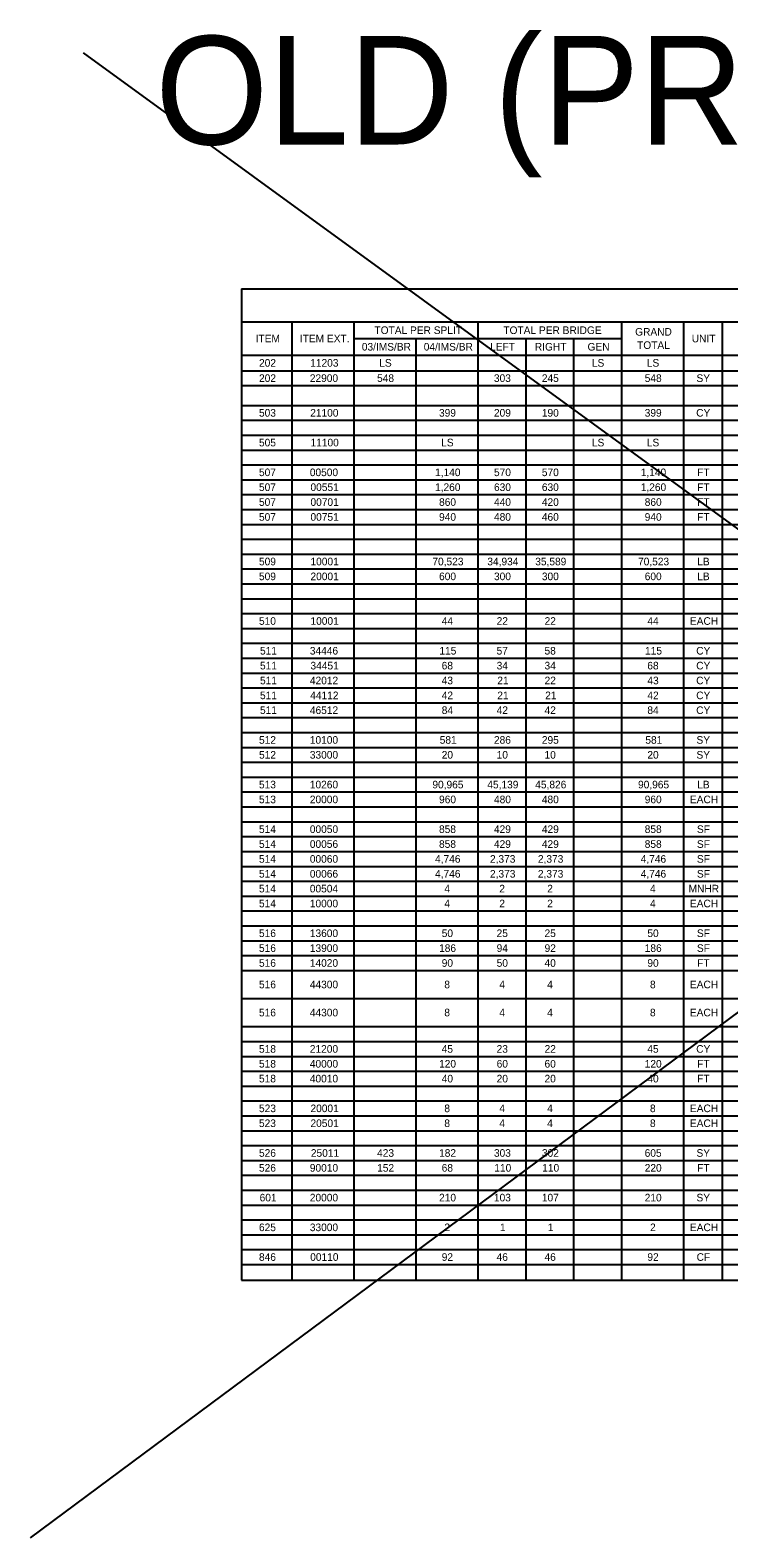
# Model space of a CAD drawing. Extents: x -62.6 to 33.3, y -2.9 to 24.9.
# Drawn here: x -62.61 to -49.74, y -2.88 to 24.89 of the extents above; entities that cross this region are included whole.
import ezdxf

# ---------------------------------------------------------------- set-up
doc = ezdxf.new("R2010")
doc.units = 0
doc.layers.add('Default', color=7, linetype='Continuous')
doc.layers.add('SH_Major_Grid_Line', color=7, linetype='Continuous')

msp = doc.modelspace()

# ---------------------------------------------------------------- linework, layer by layer
at = {"layer": 'Default'}
for p, q in [((-58.718, 20.126), (-29.957, 20.126)), ((-58.718, 20.126), (-58.718, 1.866)), ((-58.718, 19.518), (-29.957, 19.518)), ((-57.79, 19.518), (-57.79, 1.866)), ((-56.649, 19.518), (-56.649, 1.866)), ((-54.366, 19.518), (-54.366, 1.866)), ((-51.718, 19.518), (-51.718, 1.866)), ((-50.577, 19.518), (-50.577, 1.866)), ((-49.862, 19.518), (-49.862, 1.866)), ((-56.649, 19.213), (-51.718, 19.213)), ((-55.507, 19.213), (-55.507, 1.866)), ((-53.483, 19.213), (-53.483, 1.866)), ((-52.601, 19.213), (-52.601, 1.866)), ((-58.718, 18.909), (-29.957, 18.909)), ((-58.718, 18.62), (-29.957, 18.62)), ((-58.718, 18.346), (-29.957, 18.346)), ((-58.718, 17.981), (-29.957, 17.981)), ((-58.718, 17.707), (-29.957, 17.707)), ((-58.718, 17.433), (-29.957, 17.433)), ((-58.718, 17.159), (-29.957, 17.159)), ((-58.718, 16.885), (-29.957, 16.885)), ((-58.718, 16.611), (-29.957, 16.611)), ((-58.718, 16.337), (-29.957, 16.337)), ((-58.718, 16.063), (-29.957, 16.063)), ((-58.718, 15.789), (-29.957, 15.789)), ((-58.718, 15.516), (-29.957, 15.516)), ((-58.718, 15.242), (-29.957, 15.242)), ((-58.718, 14.968), (-29.957, 14.968)), ((-58.718, 14.694), (-29.957, 14.694)), ((-58.718, 14.42), (-29.957, 14.42)), ((-58.718, 14.146), (-29.957, 14.146)), ((-58.718, 13.872), (-29.957, 13.872)), ((-58.718, 13.598), (-29.957, 13.598)), ((-58.718, 13.324), (-29.957, 13.324)), ((-58.718, 13.05), (-29.957, 13.05)), ((-58.718, 12.776), (-29.957, 12.776)), ((-58.718, 12.502), (-29.957, 12.502)), ((-58.718, 12.229), (-29.957, 12.229)), ((-58.718, 11.955), (-29.957, 11.955)), ((-58.718, 11.681), (-29.957, 11.681)), ((-58.718, 11.407), (-29.957, 11.407)), ((-58.718, 11.133), (-29.957, 11.133)), ((-58.718, 10.859), (-29.957, 10.859)), ((-58.718, 10.585), (-29.957, 10.585)), ((-58.718, 10.311), (-29.957, 10.311)), ((-58.718, 10.037), (-29.957, 10.037)), ((-58.718, 9.763), (-29.957, 9.763)), ((-58.718, 9.489), (-29.957, 9.489)), ((-58.718, 9.216), (-29.957, 9.216)), ((-58.718, 8.942), (-29.957, 8.942)), ((-58.718, 8.668), (-29.957, 8.668)), ((-58.718, 8.394), (-29.957, 8.394)), ((-58.718, 8.12), (-29.957, 8.12)), ((-58.718, 7.846), (-29.957, 7.846)), ((-58.718, 7.572), (-29.957, 7.572)), ((-58.718, 7.055), (-29.957, 7.055)), ((-58.718, 6.537), (-29.957, 6.537)), ((-58.718, 6.263), (-29.957, 6.263)), ((-58.718, 5.989), (-29.957, 5.989)), ((-58.718, 5.716), (-29.957, 5.716)), ((-58.718, 5.442), (-29.957, 5.442)), ((-58.718, 5.168), (-29.957, 5.168)), ((-58.718, 4.894), (-29.957, 4.894)), ((-58.718, 4.62), (-29.957, 4.62)), ((-58.718, 4.346), (-29.957, 4.346)), ((-58.718, 4.072), (-29.957, 4.072)), ((-58.718, 3.798), (-29.957, 3.798)), ((-58.718, 3.524), (-29.957, 3.524)), ((-58.718, 3.25), (-29.957, 3.25)), ((-58.718, 2.976), (-29.957, 2.976)), ((-58.718, 2.702), (-29.957, 2.702)), ((-58.718, 2.429), (-29.957, 2.429)), ((-58.718, 2.155), (-29.957, 2.155)), ((-58.718, 1.866), (-29.957, 1.866))]:
    msp.add_line(p, q, dxfattribs=at)
at = {"layer": 'SH_Major_Grid_Line'}
for p, q in [((-25.522, 24.668), (-62.613, -2.881)), ((-61.637, 24.473), (-25.913, -1.513))]:
    msp.add_line(p, q, dxfattribs=at)

# ---------------------------------------------------------------- texts
for s, height, p in [('OLD (PRIOR TO 9-28-22)', 2, (-60.308, 22.787)), ('ITEM', 0.14, (-58.458, 19.143)), ('ITEM EXT.', 0.14, (-57.644, 19.143)), ('TOTAL PER SPLIT', 0.14, (-56.269, 19.296)), ('TOTAL PER BRIDGE', 0.14, (-53.894, 19.296)), ('GRAND ', 0.14, (-51.466, 19.266)), ('UNIT', 0.14, (-50.423, 19.143)), ('03/IMS/BR', 0.14, (-56.502, 18.991)), ('04/IMS/BR', 0.14, (-55.361, 18.991)), ('LEFT', 0.14, (-54.138, 18.991)), ('RIGHT', 0.14, (-53.314, 18.991)), ('GEN', 0.14, (-52.343, 18.991)), ('TOTAL', 0.14, (-51.43, 19.021)), ('202', 0.14, (-58.396, 18.694)), ('11203', 0.14, (-57.453, 18.694)), ('LS', 0.14, (-56.181, 18.694)), ('LS', 0.14, (-52.263, 18.694)), ('LS', 0.14, (-51.251, 18.694)), ('202', 0.14, (-58.396, 18.413)), ('22900', 0.14, (-57.46, 18.413)), ('548', 0.14, (-56.221, 18.413)), ('303', 0.14, (-54.068, 18.413)), ('245', 0.14, (-53.185, 18.413)), ('548', 0.14, (-51.29, 18.413)), ('SY', 0.14, (-50.336, 18.413)), ('503', 0.14, (-58.397, 17.774)), ('21100', 0.14, (-57.453, 17.774)), ('399', 0.14, (-55.08, 17.774)), ('209', 0.14, (-54.068, 17.774)), ('190', 0.14, (-53.185, 17.774)), ('399', 0.14, (-51.29, 17.774)), ('CY', 0.14, (-50.341, 17.774)), ('505', 0.14, (-58.397, 17.226)), ('11100', 0.14, (-57.447, 17.226)), ('LS', 0.14, (-55.04, 17.226)), ('LS', 0.14, (-52.263, 17.226)), ('LS', 0.14, (-51.251, 17.226)), ('507', 0.14, (-58.397, 16.678)), ('00500', 0.14, (-57.46, 16.678)), ('1,140', 0.14, (-55.153, 16.678)), ('570', 0.14, (-54.067, 16.678)), ('570', 0.14, (-53.185, 16.678)), ('1,140', 0.14, (-51.363, 16.678)), ('FT', 0.14, (-50.325, 16.678)), ('507', 0.14, (-58.397, 16.404)), ('00551', 0.14, (-57.448, 16.404)), ('1,260', 0.14, (-55.153, 16.404)), ('630', 0.14, (-54.067, 16.404)), ('630', 0.14, (-53.185, 16.404)), ('1,260', 0.14, (-51.363, 16.404)), ('FT', 0.14, (-50.325, 16.404)), ('507', 0.14, (-58.397, 16.13)), ('00701', 0.14, (-57.448, 16.13)), ('860', 0.14, (-55.079, 16.13)), ('440', 0.14, (-54.067, 16.13)), ('420', 0.14, (-53.185, 16.13)), ('860', 0.14, (-51.29, 16.13)), ('FT', 0.14, (-50.325, 16.13)), ('507', 0.14, (-58.397, 15.856)), ('00751', 0.14, (-57.448, 15.856)), ('940', 0.14, (-55.079, 15.856)), ('480', 0.14, (-54.067, 15.856)), ('460', 0.14, (-53.185, 15.856)), ('940', 0.14, (-51.29, 15.856)), ('FT', 0.14, (-50.325, 15.856)), ('509', 0.14, (-58.397, 15.035)), ('10001', 0.14, (-57.448, 15.035)), ('70,523', 0.14, (-55.202, 15.035)), ('34,934', 0.14, (-54.19, 15.035)), ('35,589', 0.14, (-53.307, 15.035)), ('70,523', 0.14, (-51.413, 15.035)), ('LB', 0.14, (-50.322, 15.035)), ('509', 0.14, (-58.397, 14.761)), ('20001', 0.14, (-57.448, 14.761)), ('600', 0.14, (-55.079, 14.761)), ('300', 0.14, (-54.067, 14.761)), ('300', 0.14, (-53.185, 14.761)), ('600', 0.14, (-51.29, 14.761)), ('LB', 0.14, (-50.322, 14.761)), ('510', 0.14, (-58.397, 13.939)), ('10001', 0.14, (-57.448, 13.939)), ('44', 0.14, (-55.03, 13.939)), ('22', 0.14, (-54.018, 13.939)), ('22', 0.14, (-53.135, 13.939)), ('44', 0.14, (-51.241, 13.939)), ('EACH', 0.14, (-50.457, 13.939)), ('511', 0.14, (-58.378, 13.391)), ('34446', 0.14, (-57.46, 13.391)), ('115', 0.14, (-55.073, 13.391)), ('57', 0.14, (-54.019, 13.391)), ('58', 0.14, (-53.136, 13.391)), ('115', 0.14, (-51.284, 13.391)), ('CY', 0.14, (-50.341, 13.391)), ('511', 0.14, (-58.378, 13.117)), ('34451', 0.14, (-57.448, 13.117)), ('68', 0.14, (-55.031, 13.117)), ('34', 0.14, (-54.018, 13.117)), ('34', 0.14, (-53.136, 13.117)), ('68', 0.14, (-51.242, 13.117)), ('CY', 0.14, (-50.341, 13.117)), ('511', 0.14, (-58.378, 12.843)), ('42012', 0.14, (-57.459, 12.843)), ('43', 0.14, (-55.031, 12.843)), ('21', 0.14, (-54.006, 12.843)), ('22', 0.14, (-53.135, 12.843)), ('43', 0.14, (-51.241, 12.843)), ('CY', 0.14, (-50.341, 12.843)), ('511', 0.14, (-58.378, 12.569)), ('44112', 0.14, (-57.453, 12.569)), ('42', 0.14, (-55.03, 12.569)), ('21', 0.14, (-54.006, 12.569)), ('21', 0.14, (-53.124, 12.569)), ('42', 0.14, (-51.241, 12.569)), ('CY', 0.14, (-50.341, 12.569)), ('511', 0.14, (-58.378, 12.296)), ('46512', 0.14, (-57.459, 12.296)), ('84', 0.14, (-55.03, 12.296)), ('42', 0.14, (-54.018, 12.296)), ('42', 0.14, (-53.135, 12.296)), ('84', 0.14, (-51.241, 12.296)), ('CY', 0.14, (-50.341, 12.296)), ('512', 0.14, (-58.396, 11.748)), ('10100', 0.14, (-57.46, 11.748)), ('581', 0.14, (-55.067, 11.748)), ('286', 0.14, (-54.068, 11.748)), ('295', 0.14, (-53.185, 11.748)), ('581', 0.14, (-51.278, 11.748)), ('SY', 0.14, (-50.336, 11.748)), ('512', 0.14, (-58.396, 11.474)), ('33000', 0.14, (-57.46, 11.474)), ('20', 0.14, (-55.03, 11.474)), ('10', 0.14, (-54.018, 11.474)), ('10', 0.14, (-53.136, 11.474)), ('20', 0.14, (-51.241, 11.474)), ('SY', 0.14, (-50.336, 11.474)), ('513', 0.14, (-58.397, 10.926)), ('10260', 0.14, (-57.46, 10.926)), ('90,965', 0.14, (-55.202, 10.926)), ('45,139', 0.14, (-54.19, 10.926)), ('45,826', 0.14, (-53.307, 10.926)), ('90,965', 0.14, (-51.413, 10.926)), ('LB', 0.14, (-50.322, 10.926)), ('513', 0.14, (-58.397, 10.652)), ('20000', 0.14, (-57.46, 10.652)), ('960', 0.14, (-55.079, 10.652)), ('480', 0.14, (-54.067, 10.652)), ('480', 0.14, (-53.185, 10.652)), ('960', 0.14, (-51.29, 10.652)), ('EACH', 0.14, (-50.457, 10.652)), ('514', 0.14, (-58.397, 10.104)), ('00050', 0.14, (-57.46, 10.104)), ('858', 0.14, (-55.08, 10.104)), ('429', 0.14, (-54.068, 10.104)), ('429', 0.14, (-53.185, 10.104)), ('858', 0.14, (-51.29, 10.104)), ('SF', 0.14, (-50.328, 10.104)), ('514', 0.14, (-58.397, 9.83)), ('00056', 0.14, (-57.46, 9.83)), ('858', 0.14, (-55.08, 9.83)), ('429', 0.14, (-54.068, 9.83)), ('429', 0.14, (-53.185, 9.83)), ('858', 0.14, (-51.29, 9.83)), ('SF', 0.14, (-50.328, 9.83)), ('514', 0.14, (-58.397, 9.556)), ('00060', 0.14, (-57.46, 9.556)), ('4,746', 0.14, (-55.153, 9.556)), ('2,373', 0.14, (-54.141, 9.556)), ('2,373', 0.14, (-53.258, 9.556)), ('4,746', 0.14, (-51.364, 9.556)), ('SF', 0.14, (-50.328, 9.556)), ('514', 0.14, (-58.397, 9.282)), ('00066', 0.14, (-57.46, 9.282)), ('4,746', 0.14, (-55.153, 9.282)), ('2,373', 0.14, (-54.141, 9.282)), ('2,373', 0.14, (-53.258, 9.282)), ('4,746', 0.14, (-51.364, 9.282)), ('SF', 0.14, (-50.328, 9.282)), ('514', 0.14, (-58.397, 9.009)), ('00504', 0.14, (-57.46, 9.009)), ('4', 0.14, (-54.981, 9.009)), ('2', 0.14, (-53.969, 9.009)), ('2', 0.14, (-53.086, 9.009)), ('4', 0.14, (-51.192, 9.009)), ('MNHR', 0.14, (-50.482, 9.009)), ('514', 0.14, (-58.397, 8.735)), ('10000', 0.14, (-57.46, 8.735)), ('4', 0.14, (-54.981, 8.735)), ('2', 0.14, (-53.969, 8.735)), ('2', 0.14, (-53.086, 8.735)), ('4', 0.14, (-51.192, 8.735)), ('EACH', 0.14, (-50.457, 8.735)), ('516', 0.14, (-58.397, 8.187)), ('516', 0.14, (-58.397, 7.913)), ('13600', 0.14, (-57.46, 8.187)), ('13900', 0.14, (-57.46, 7.913)), ('186', 0.14, (-55.079, 7.913)), ('50', 0.14, (-55.03, 8.187)), ('25', 0.14, (-54.019, 8.187)), ('94', 0.14, (-54.018, 7.913)), ('25', 0.14, (-53.136, 8.187)), ('92', 0.14, (-53.135, 7.913)), ('186', 0.14, (-51.29, 7.913)), ('50', 0.14, (-51.241, 8.187)), ('SF', 0.14, (-50.328, 8.187)), ('SF', 0.14, (-50.328, 7.913)), ('516', 0.14, (-58.397, 7.639)), ('14020', 0.14, (-57.46, 7.639)), ('90', 0.14, (-55.03, 7.639)), ('50', 0.14, (-54.018, 7.639)), ('40', 0.14, (-53.136, 7.639)), ('90', 0.14, (-51.241, 7.639)), ('FT', 0.14, (-50.325, 7.639)), ('516', 0.14, (-58.397, 7.243)), ('44300', 0.14, (-57.46, 7.243)), ('8', 0.14, (-54.982, 7.243)), ('4', 0.14, (-53.969, 7.243)), ('4', 0.14, (-53.087, 7.243)), ('8', 0.14, (-51.193, 7.243)), ('EACH', 0.14, (-50.457, 7.243)), ('516', 0.14, (-58.397, 6.726)), ('44300', 0.14, (-57.46, 6.726)), ('8', 0.14, (-54.982, 6.726)), ('4', 0.14, (-53.969, 6.726)), ('4', 0.14, (-53.087, 6.726)), ('8', 0.14, (-51.193, 6.726)), ('EACH', 0.14, (-50.457, 6.726)), ('518', 0.14, (-58.397, 6.056)), ('21200', 0.14, (-57.46, 6.056)), ('45', 0.14, (-55.031, 6.056)), ('23', 0.14, (-54.019, 6.056)), ('22', 0.14, (-53.135, 6.056)), ('45', 0.14, (-51.242, 6.056)), ('CY', 0.14, (-50.341, 6.056)), ('518', 0.14, (-58.397, 5.782)), ('40000', 0.14, (-57.46, 5.782)), ('120', 0.14, (-55.079, 5.782)), ('60', 0.14, (-54.018, 5.782)), ('60', 0.14, (-53.136, 5.782)), ('120', 0.14, (-51.29, 5.782)), ('FT', 0.14, (-50.325, 5.782)), ('518', 0.14, (-58.397, 5.509)), ('40010', 0.14, (-57.46, 5.509)), ('40', 0.14, (-55.03, 5.509)), ('20', 0.14, (-54.018, 5.509)), ('20', 0.14, (-53.136, 5.509)), ('40', 0.14, (-51.241, 5.509)), ('FT', 0.14, (-50.325, 5.509)), ('523', 0.14, (-58.397, 4.961)), ('20001', 0.14, (-57.448, 4.961)), ('8', 0.14, (-54.982, 4.961)), ('4', 0.14, (-53.969, 4.961)), ('4', 0.14, (-53.087, 4.961)), ('8', 0.14, (-51.193, 4.961)), ('EACH', 0.14, (-50.457, 4.961)), ('523', 0.14, (-58.397, 4.687)), ('20501', 0.14, (-57.448, 4.687)), ('8', 0.14, (-54.982, 4.687)), ('4', 0.14, (-53.969, 4.687)), ('4', 0.14, (-53.087, 4.687)), ('8', 0.14, (-51.193, 4.687)), ('EACH', 0.14, (-50.457, 4.687)), ('526', 0.14, (-58.397, 4.139)), ('25011', 0.14, (-57.441, 4.139)), ('423', 0.14, (-56.221, 4.139)), ('182', 0.14, (-55.079, 4.139)), ('303', 0.14, (-54.068, 4.139)), ('302', 0.14, (-53.184, 4.139)), ('605', 0.14, (-51.291, 4.139)), ('SY', 0.14, (-50.336, 4.139)), ('526', 0.14, (-58.397, 3.865)), ('90010', 0.14, (-57.46, 3.865)), ('152', 0.14, (-56.22, 3.865)), ('68', 0.14, (-55.031, 3.865)), ('110', 0.14, (-54.061, 3.865)), ('110', 0.14, (-53.178, 3.865)), ('220', 0.14, (-51.29, 3.865)), ('FT', 0.14, (-50.325, 3.865)), ('601', 0.14, (-58.385, 3.317)), ('20000', 0.14, (-57.46, 3.317)), ('210', 0.14, (-55.079, 3.317)), ('103', 0.14, (-54.068, 3.317)), ('107', 0.14, (-53.185, 3.317)), ('210', 0.14, (-51.29, 3.317)), ('SY', 0.14, (-50.336, 3.317)), ('625', 0.14, (-58.397, 2.769)), ('33000', 0.14, (-57.46, 2.769)), ('2', 0.14, (-54.981, 2.769)), ('1', 0.14, (-53.957, 2.769)), ('1', 0.14, (-53.075, 2.769)), ('2', 0.14, (-51.192, 2.769)), ('EACH', 0.14, (-50.457, 2.769)), ('846', 0.14, (-58.397, 2.222)), ('00110', 0.14, (-57.453, 2.222)), ('92', 0.14, (-55.03, 2.222)), ('46', 0.14, (-54.019, 2.222)), ('46', 0.14, (-53.136, 2.222)), ('92', 0.14, (-51.241, 2.222)), ('CF', 0.14, (-50.333, 2.222))]:
    msp.add_text(s, height=height, dxfattribs=at).set_placement(p)

doc.saveas('drawing.dxf')
